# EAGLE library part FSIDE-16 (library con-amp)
AMP connector
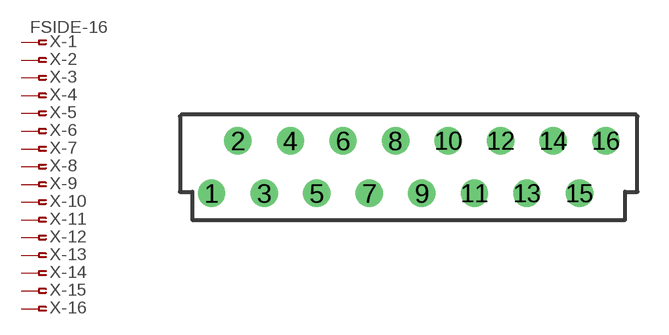
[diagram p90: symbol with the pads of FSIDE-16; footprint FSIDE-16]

Designator prefix X; gates -1=PIN-FV -2=PIN-F -3=PIN-F -4=PIN-F -5=PIN-F -6=PIN-F -7=PIN-F -8=PIN-F -9=PIN-F -10=PIN-F -11=PIN-F -12=PIN-F -13=PIN-F -14=PIN-F -15=PIN-F -16=PIN-F

## FSIDE-16 (OC_FARNELL: unknown; OC_NEWARK: unknown)  [FSIDE-16]
1  -1:1  pas
2  -2:1  pas
3  -3:1  pas
4  -4:1  pas
5  -5:1  pas
6  -6:1  pas
7  -7:1  pas
8  -8:1  pas
9  -9:1  pas
10  -10:1  pas
11  -11:1  pas
12  -12:1  pas
13  -13:1  pas
14  -14:1  pas
15  -15:1  pas
16  -16:1  pas

## Footprint FSIDE-16 (pad centres in mm)
AMP connector
drill 0.813 round: 1 -9.525,-1.27; 2 -8.255,1.27; 3 -6.985,-1.27; 4 -5.715,1.27; 5 -4.445,-1.27; 6 -3.175,1.27; 7 -1.905,-1.27; 8 -0.635,1.27; 9 0.635,-1.27; 10 1.905,1.27; 11 3.175,-1.27; 12 4.445,1.27; 13 5.715,-1.27; 14 6.985,1.27; 15 8.255,-1.27; 16 9.525,1.27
